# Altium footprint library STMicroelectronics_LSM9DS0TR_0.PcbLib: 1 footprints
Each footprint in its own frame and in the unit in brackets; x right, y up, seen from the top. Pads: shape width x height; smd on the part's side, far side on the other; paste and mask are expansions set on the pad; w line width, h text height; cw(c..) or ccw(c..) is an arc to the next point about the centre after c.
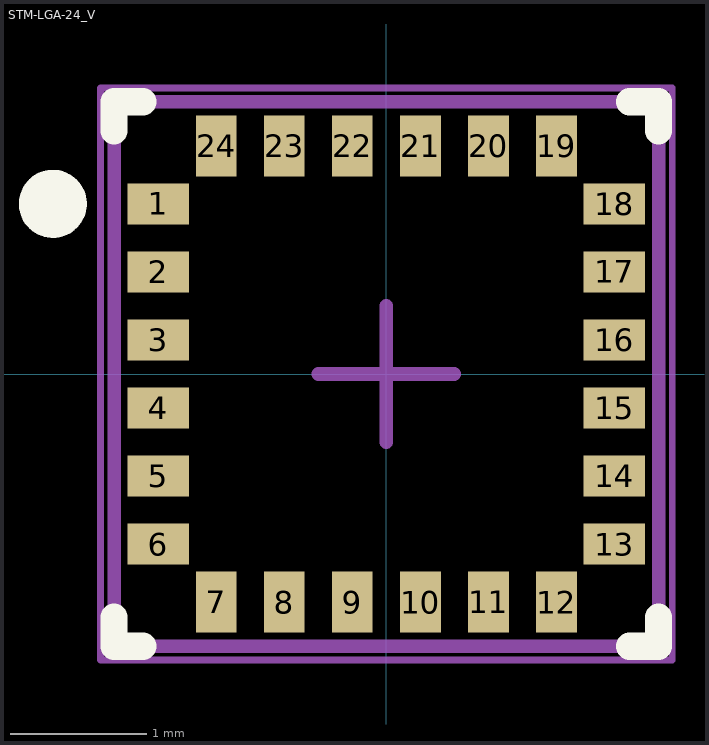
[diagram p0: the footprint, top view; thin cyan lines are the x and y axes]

## STM-LGA-24_V [mm] "LGA, 24-Leads, Body 4x4mm, Pitch 0.5mm"
height 1.07
pads (24):
  rect 0.45x0.3 smd mask+0.05: 1(-1.675,1.25) 2(-1.675,0.75) 3(-1.675,0.25) 4(-1.675,-0.25) 5(-1.675,-0.75) 6(-1.675,-1.25) 13(1.675,-1.25) 14(1.675,-0.75) 15(1.675,-0.25) 16(1.675,0.25) 17(1.675,0.75) 18(1.675,1.25)
  rect 0.3x0.45 smd mask+0.05: 7(-1.25,-1.675) 8(-0.75,-1.675) 9(-0.25,-1.675) 10(0.25,-1.675) 11(0.75,-1.675) 12(1.25,-1.675) 19(1.25,1.675) 20(0.75,1.675) 21(0.25,1.675) 22(-0.25,1.675) 23(-0.75,1.675) 24(-1.25,1.675)
Top Overlay:
  circle w0.25: c-2.45,1.25 r0.125
  lines w0.2: -2,-1.787 -2,-2 -1.787,-2 ; -2,1.787 -2,2 -1.787,2 ; 1.787,-2 2,-2 2,-1.787 ; 1.787,2 2,2 2,1.787
Mechanical 13:
  lines w0.1: -2,-2 2,-2 2,2 -2,2 -2,-2
Mechanical 15:
  lines w0.05: -2.1,-2.1 2.1,-2.1 2.1,2.1 -2.1,2.1 -2.1,-2.1
  lines w0.1: -0.5,0 0.5,0 ; 0,-0.5 0,0.5
3D body: height 1.07, standoff 0, extent -2,-2 2,2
